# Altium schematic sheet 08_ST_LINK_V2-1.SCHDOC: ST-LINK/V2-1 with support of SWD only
size A4; Date: 17-03-2016; Author: A.B; CompanyName: STMicroelectronics; Organization: Microcontrollers Division; Address1: 12, Rue Jules HOROWITZ; Address2: 38019 Grenoble; Address3: FRANCE; DocumentNumber: 11; Revision: E-01; SheetNumber: 11; SheetTotal: 12; Project: STM32F413H-DISCO
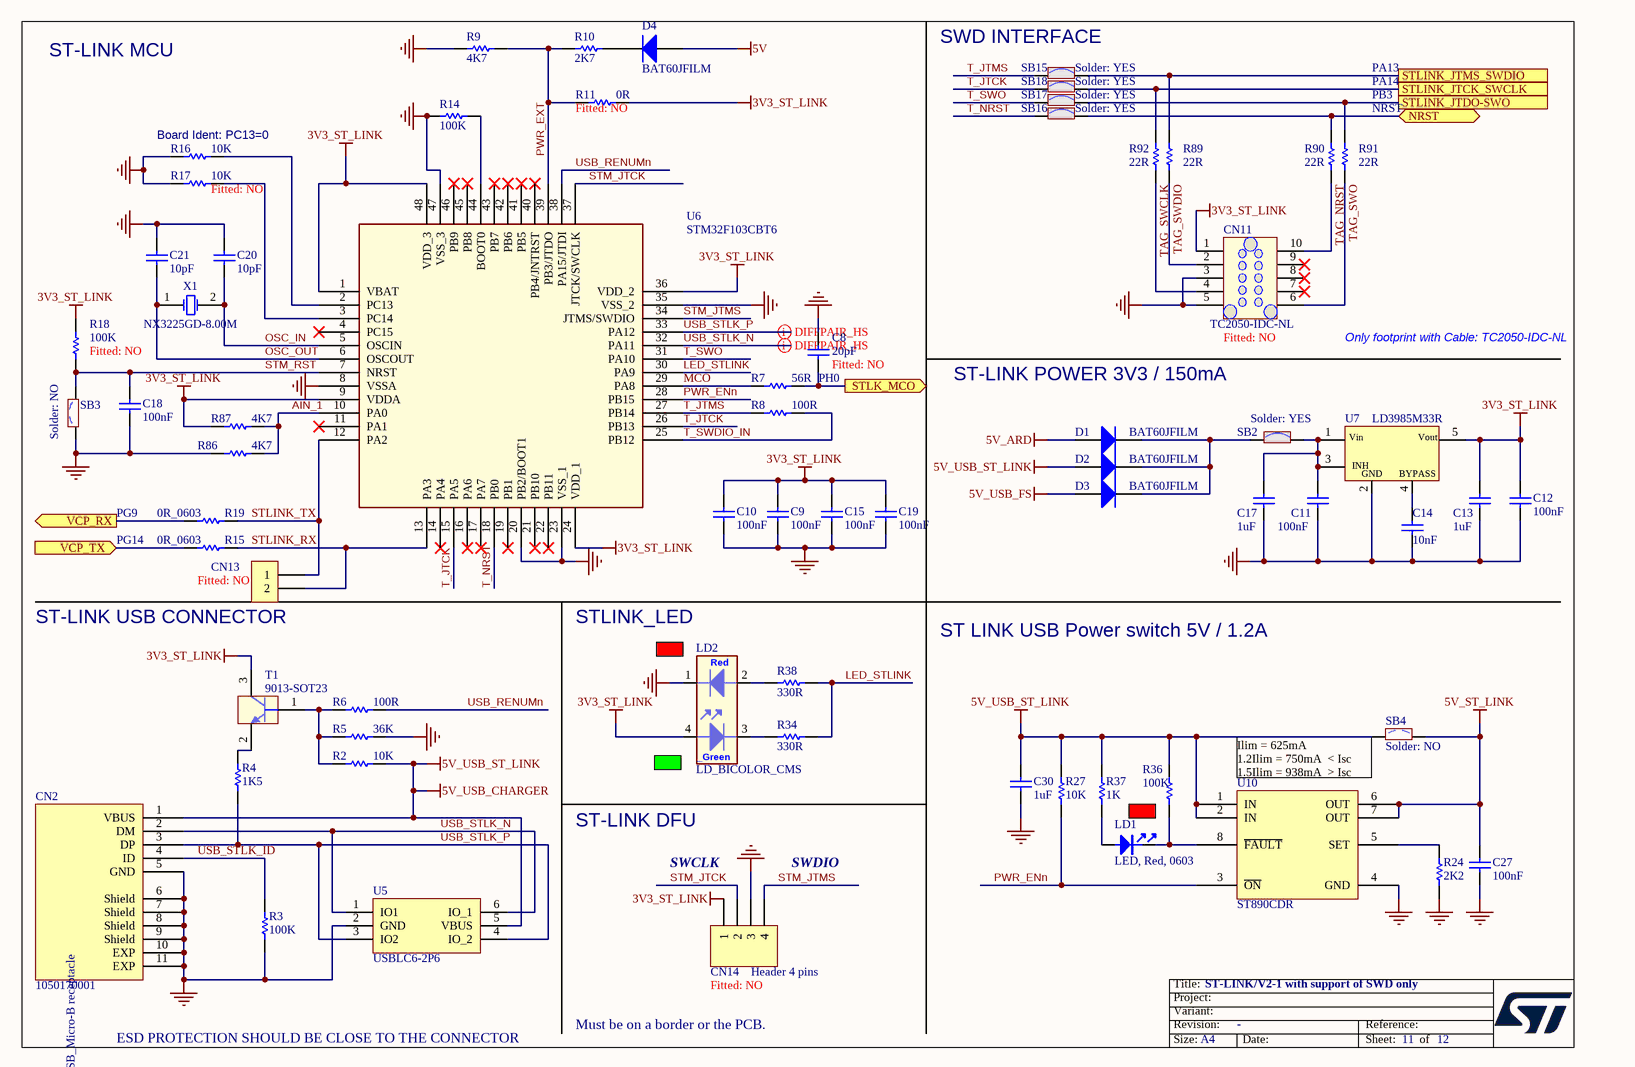
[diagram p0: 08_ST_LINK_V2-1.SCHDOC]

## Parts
C8  20pF  Fitted: NO  [C0402]
C9  100nF  [C0402]
C10  100nF  [C0402]
C11  100nF  [C0402]
C12  100nF  [C0402]
C13  1uF  [C0603]
C14  10nF  [C0603]
C15  100nF  [C0402]
C17  1uF  [C0603]
C18  100nF  [C0402]
C19  100nF  [C0402]
C20  10pF  [C0402]
C21  10pF  [C0402]
C27  100nF  [C0402]
C30  1uF  [C0603]
CN2  1050170001  [CON_USBMICROB_MOLEX_105017-0001_H2P90]
CN11  TC2050-IDC-NL  Fitted: NO  [CON_TAG-C_TC2050-IDC-NL]
CN13  Fitted: NO  [CON_SAMTEC_TSW-102-07-G-S]  (hidden comment: header 2 pins 2.54mm)
CN14  Header 4 pins  Fitted: NO  [CON_SAMTEC_TSW-104-07-G-S]
D1  BAT60JFILM  [DIO_SOD323]
D2  BAT60JFILM  [DIO_SOD323]
D3  BAT60JFILM  [DIO_SOD323]
D4  BAT60JFILM  [DIO_SOD323]
LD1  LED, Red, 0603  [LED_0603_RED]
LD2  LD_BICOLOR_CMS  [LED_BI-GR_HSMF-A201-A00J1]
R2  10K  [R0402]
R3  100K  [R0402]
R4  1K5  [R0402]
R5  36K  [R0402]
R6  100R  [R0402]
R7  56R  [R0402]
R8  100R  [R0402]
R9  4K7  [R0402]
R10  2K7  [R0402]
R11  0R  Fitted: NO  [R0402]
R14  100K  [R0402]
R15  0R_0603  [R0603]
R16  10K  [R0402]
R17  10K  Fitted: NO  [R0402]
R18  100K  Fitted: NO  [R0402]
R19  0R_0603  [R0603]
R24  2K2  [R0402]
R27  10K  [R0402]
R34  330R  [R0402]
R36  100K  [R0402]
R37  1K  [R0402]
R38  330R  [R0402]
R86  4K7  [R0402]
R87  4K7  [R0402]
R89  22R  [R0603]
R90  22R  [R0603]
R91  22R  [R0603]
R92  22R  [R0603]
SB2  Solder: YES  [SOLDER-BRIDGE_R0603-0R]  (hidden comment: SB_ON)
SB3  Solder: NO  [SOLDER-BRIDGE_R0603-0R]  (hidden comment: SB_OFF)
SB4  Solder: NO  [SOLDER-BRIDGE_R0603-0R]  (hidden comment: SB_OFF)
SB15  Solder: YES  [SOLDER-BRIDGE_R0603-0R]  (hidden comment: SB_ON)
SB16  Solder: YES  [SOLDER-BRIDGE_R0603-0R]  (hidden comment: SB_ON)
SB17  Solder: YES  [SOLDER-BRIDGE_R0603-0R]  (hidden comment: SB_ON)
SB18  Solder: YES  [SOLDER-BRIDGE_R0603-0R]  (hidden comment: SB_ON)
T1  9013-SOT23  [NPN_SOT23]
U5  USBLC6-2P6  [ESD_SOT666]
U6  STM32F103CBT6  [ICC_LQFP48_7X7_P050]
U7  LD3985M33R  [REG_SOT23-5L]
U10  ST890CDR  [ICC_SO8_5X4_P127]
X1  NX3225GD-8.00M  [CRY_NX3225GD_2P]

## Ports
NRST (bidir), STLINK_JTCK_SWCLK, STLINK_JTDO-SWO, STLINK_JTMS_SWDIO, STLK_MCO (out), VCP_RX (out), VCP_TX (in)

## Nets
3V3_ST_LINK: C9.2 C10.2 C12.2 C13.2 C15.2 C19.2 CN11.1 CN14.1 LD2.4 R11.2 R18.2 R87.1 T1.3(C) U6.1(VBAT) U6.9(VDDA) U6.24(VDD_1) U6.36(VDD_2) U6.48(VDD_3) U7.5(Vout)
5V: D4.1(A)
5V_ARD: D1.1(A)
5V_ST_LINK: C27.2 SB4.2 U10.6(OUT) U10.7(OUT)
5V_USB_CHARGER: C30.2 CN2.1(VBUS) D2.1(A) R2.1 R27.2 R36.2 R37.2 SB4.1 U5.5(VBUS) U10.1(IN) U10.2(IN)  [also labelled 5V_USB_ST_LINK]
5V_USB_FS: D3.1(A)
GND: C8.1 C9.1 C10.1 C11.1 C12.1 C13.1 C14.1 C15.1 C17.1 C18.1 C19.1 C20.2 C21.2 C27.1 C30.1 CN2.5(GND) CN2.6(Shield) CN2.7(Shield) CN2.8(Shield) CN2.9(Shield) CN2.10(EXP) CN2.11(EXP) CN11.3 CN11.5 CN14.3 LD2.1 R3.1 R5.1 R9.1 R14.1 R16.2 R17.2 R24.1 R86.1 SB3.1 U5.2(GND) U6.8(VSSA) U6.20(PB2/BOOT1) U6.23(VSS_1) U6.35(VSS_2) U6.47(VSS_3) U7.2(GND) U10.4(GND)
AIN_1: R86.2 R87.2 U6.10(PA0)
LED_STLINK: R34.2 R38.2 U6.30(PA9)
MCO: R7.1 U6.29(PA8)
NRST: R90.2 SB16.2 ; port NRST
OSC_IN: C20.1 U6.5(OSCIN) X1.2(OSC2)
OSC_OUT: C21.1 U6.6(OSCOUT) X1.1(OSC1)
PWR_ENn: R27.1 U6.28(PB15) U10.3(~{ON})
PWR_EXT: R9.2 R10.1 R11.1 U6.39(PB3/JTDO)
STLINK_JTCK_SWCLK: R92.2 SB18.2 ; port STLINK_JTCK_SWCLK
STLINK_JTDO-SWO: R91.2 SB17.2 ; port STLINK_JTDO-SWO
STLINK_JTMS_SWDIO: R89.2 SB15.2 ; port STLINK_JTMS_SWDIO
STLINK_RX: CN13.2 R15.2 U6.13(PA3)
STLINK_TX: CN13.1 R19.2 U6.12(PA2)
STLK_MCO: C8.2 R7.2 ; port STLK_MCO
STM_JTCK: CN14.2 U6.37(JTCK/SWCLK)
STM_JTMS: CN14.4 U6.34(JTMS/SWDIO)
STM_RST: C18.2 R18.1 SB3.2 U6.7(NRST)
T_JTCK: SB18.1 U6.15(PA5) U6.26(PB13)
T_JTMS: R8.1 SB15.1 U6.27(PB14)
T_NRST: SB16.1 U6.18(PB0)
T_SWDIO_IN: R8.2 U6.25(PB12)
T_SWO: SB17.1 U6.31(PA10)
TAG_NRST: CN11.10 R90.1
TAG_SWCLK: CN11.4 R92.1
TAG_SWDIO: CN11.2 R89.1
TAG_SWO: CN11.6 R91.1
USB_RENUMn: R6.2 U6.38(PA15/JTDI)
USB_STLK_ID: CN2.4(ID) R3.2
USB_STLK_N: CN2.2(DM) U5.1(IO1) U5.6(IO_1) U6.32(PA11)
USB_STLK_P: CN2.3(DP) R4.1 U5.3(IO2) U5.4(IO_2) U6.33(PA12)
VCP_RX: R19.1 ; port VCP_RX
VCP_TX: R15.1 ; port VCP_TX
NetC11_2: C11.2 C17.2 SB2.2 U7.1(Vin) U7.3(CE)
NetC14_2: C14.2 U7.4(BYPASS)
NetD1_2: D1.2(K) D2.2(K) D3.2(K) SB2.1
NetD4_2: D4.2(K) R10.2
NetLD1_1: LD1.1 R37.1
NetLD1_2: LD1.2 R36.1 U10.8(~{FAULT})
NetLD2_2: LD2.2 R38.1
NetLD2_3: LD2.3 R34.1
NetR2_2: R2.2 R5.2 R6.1 T1.1(B)
NetR4_2: R4.2 T1.2(E)
NetR14_2: R14.2 U6.44(BOOT0)
NetR16_1: R16.1 U6.2(PC13)
NetR17_1: R17.1 U6.3(PC14)
NetR24_2: R24.2 U10.5(SET)

Not connected (* = marked no-connect by the designer): CN11 7* 8* 9*; U6 4(PC15)* 11(PA1)* 14(PA4)* 16(PA6)* 17(PA7)* 19(PB1)* 21(PB10)* 22(PB11)* 40(PB4/JNTRST)* 41(PB5)* 42(PB6)* 43(PB7)* 45(PB8)* 46(PB9)*

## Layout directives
differential pair: USB_STLK_N, USB_STLK_P

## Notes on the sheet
- ST-LINK MCU
- SWD INTERFACE
- PA14
- PA13
- PB3
- NRST
- (near R16) Board Ident: PC13=0
- (near C8) PH0
- ST-LINK POWER 3V3 / 150mA
- Only footprint with Cable: TC2050-IDC-NL
- PG9
- PG14
- ST-LINK USB CONNECTOR
- STLINK_LED
- ST LINK USB Power switch 5V / 1.2A
- (near SB4) Ilim = 625mA
  1.2Ilim = 750mA  < Isc
  1.5Ilim = 938mA  > Isc
- ST-LINK DFU
- SWCLK
- SWDIO
- ESD PROTECTION SHOULD BE CLOSE TO THE CONNECTOR
- Must be on a border or the PCB.

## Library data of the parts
C8 = Cap_20pF_NPO_5%_0402: Capacitor,20pF,50V,NPO,5%,0402,YAGEO; Manuf_Part_1: CC0402JRNPO9BN200; Ordered_By: Subcon
C9-C12 C15 C18 C19 C27 = Cap_100nF_X7R_10%_0402: Capacitor,100nF,16V,X7R,10%,0402,YAGEO; Manuf_Part_1: CC0402KRX7R7BB104; Fitted: YES; Ordered_By: Subcon
C13 C17 C30 = Cap_1uF_X5R_10%_0603: Capacitor,1uF,16V,X5R,10%,0603,YAGEO; Manuf_Part_1: CC0603KRX5R7BB105; Fitted: YES; Ordered_By: Subcon
C14 = Cap_10nF_X7R_10%_0603: Capacitor,10nF,50V,X7R,10%,0603,YAGEO; Manuf_Part_1: CC0603KRX7R9BB103; Fitted: YES; Ordered_By: Subcon
C20 C21 = Cap_10pF_NPO_5%_0402: Capacitor,10pF,50V,NPO,5%,0402,YAGEO; Manuf_Part_1: CC0402JRNPO9BN100; Fitted: YES; Ordered_By: subcon
CN2 = 1050170001: USB-MICRO-B, 1050170001, SMT, MOLEX; Fitted: YES; Ordered_By: Subcon
CN11 = Tag-10-C: Tag_Connector Header, 10-Pin, Dual row No legs; Manuf_Part_1: TC2050-IDC-NL-FP; Ordered_By: Subcon
CN13 = Header 2 pins: Manuf_1: SAMTEC; Manuf_Part_2: 4711955140470; Manuf_2: KONTEC; Manuf_Part_1: TSW-102-07-x-S; Order_Code: 423-2841; Ordered_By: Subcon
CN14 = Header 4: Header, 4-Pin; Manuf_1: SAMTEC; Manuf_Part_1: TSW-104-07-x-S; Ordered_By: Subcon
D1-D4 = BAT60JFILM: Manuf_1: STM; ECCN_US/EU: EAR99/NEC; Ref St: 9151097; Fitted: YES
LD1 = LED_red: Manuf_1: everlight; Manuf_Part_1: 19-213-R6C-AP1Q2B/3T; ECCN_US/EU: EAR99/NEC; Fitted: YES; Ordered_By: Subcon
LD2 = LD_BICOLOR_CMS: Bicolor Led; Manuf_Part_1: HSMF-A201-A00J1; Manuf_1: Avago Technologies; Manuf_2: everluck; Manuf_Part_2: LE-RGW35280; ECCN_US/EU: EAR99/NEC; Fitted: YES; Ordered_By: Subcon
R2 R16 R27 = Res_10K_1%_0402: Resistor,10K,0402,1%,YAGEO; Manuf_Part_1: RC0402FR-0710KL; Fitted: YES; Ordered_By: subcon
R3 R36 = Res_100K_1%_0402: Resistor,100K,0402,1%,YAGEO; Manuf_Part_2: RT0402FRE07100KL; Manuf_Part_1: RC0402FR-07100KL; Fitted: YES; Ordered_By: Subcon
R4 = Res_1K5_1%_0402: Resistor,1K5,0402,1%,YAGEO; Manuf_Part_1: RC0402FR-071K5L; Fitted: YES; Ordered_By: Subcon
R5 = Res_36K_1%_0402: Resistor,36K,0402,1%,YAGEO; Manuf_Part_1: RC0402FR-0736KL; Fitted: YES; Ordered_By: Subcon
R6 R8 = Res_100_1%_0402: Resistor,100R,0402,1%,YAGEO; Manuf_Part_1: RC0402FR-07100RL; Fitted: YES; Order_Code: 9239111; Ordered_By: Subcon
R7 = Res_56_1%_0402: Resistor,56R,0402,1%,YAGEO; Manuf_Part_1: RC0402FR-0756RL; Fitted: YES; Order_Code: 9239081RL; Ordered_By: Subcon
R9 = Res_4K7_1%_0402: Resistor,4K7,0402,1%,YAGEO; Manuf_Part_1: RC0402FR-074K7L; Manuf_Part_2: RT0402FRE074K7L; Fitted: YES; Ordered_By: Subcon
R10 = Res_2K7_1%_0402: Resistor,2K7,0402,1%,YAGEO; Manuf_Part_1: RC0402FR-072K7L; Fitted: YES; Ordered_By: Subcon
R11 = Res_0_5%_0402: Resistor,0R,0402,5%,YAGEO; Manuf_Part_1: RC0402JR-070RL; Order_Code: 2363467; Ordered_By: Subcon
R14 = Res_100K_1%_0402: Resistor,100K,0402,1%,YAGEO; Manuf_Part_1: RC0402FR-07100KL; Manuf_Part_2: RT0402FRE07100KL; Fitted: YES; Ordered_By: Subcon
R15 R19 = Res_0_5%_0603: Resistor,0R,0603,5%,YAGEO; Manuf_Part_1: RC0603JR-070RL; Fitted: YES; Order_Code: 2363481; Ordered_By: subcon
R17 = Res_10K_1%_0402: Resistor,10K,0402,1%,YAGEO; Manuf_Part_1: RC0402FR-0710KL; Ordered_By: subcon
R18 = Res_100K_1%_0402: Resistor,100K,0402,1%,YAGEO; Manuf_Part_1: RC0402FR-07100KL; Manuf_Part_2: RT0402FRE07100KL; Ordered_By: Subcon
R24 = Res_2K2_1%_0402: Resistor,2K2,0402,1%,YAGEO; Manuf_Part_1: RC0402FR-072K2L; Fitted: YES; Ordered_By: Subcon
R34 R38 = Res_330_1%_0402: Resistor,330R,0402,1%,YAGEO; Manuf_Part_1: RC0402FR-07330RL; Fitted: YES; Ordered_By: Subcon
R37 = Res_1K_1%_0402: Resistor,1K,0402,1%,YAGEO; Manuf_Part_1: RC0402FR-071KL; Fitted: YES; Ordered_By: Subcon
R86 R87 = Res_4K7_1%_0402: Resistor,4K7,0402,1%,YAGEO; Manuf_Part_2: RT0402FRE074K7L; Manuf_Part_1: RC0402FR-074K7L; Fitted: YES; Ordered_By: Subcon
R89-R92 = Res_22_1%_0603: Resistor,22R,0603,1%,Yageo; Manuf_Part_1: RC0603FR-0722RL; Fitted: YES; Ordered_By: Subcon
SB2 SB15-SB18 = SB_ON: Solder Bridge ON; Ordered_by: Subcon
SB3 SB4 = SB_OFF: Solder Bridge OFF; Fitted: NO; Ordered_By: Subcon
T1 = 9013-SOT23: NPN Bipolar Transistor; Manuf_1: NXP; Manuf_Part_1: BSR14; ECCN_US/EU: EAR99/NEC; Fitted: YES; Order_Code: 1081310; Ordered_By: Subcon
U5 = USBLC6-2P6: USB ESD protection; Ordered_By: STM; ECCN_US/EU: EAR99; Fitted: YES
U6 = STM32F103CBT6: Medium-density performance line ARM-based 32-bit MCU with 128KB Flash; Manuf_1: STM; ECCN_US/EU: 3A991A2/NEC; Fitted: YES
U7 = LD3985M33R: Ultra low drop-low noise BiCMOS voltage, regulators low ESR capacitors compatible; Manuf_1: STM; Ref St: 9176161; ECCN_US/EU: EAR99/NEC; Fitted: YES
U10 = ST890CDR: 1.2 A current limited high-side power switch with thermal shutdown; Manuf_1: STM; ECCN_US/EU: EAR99/NEC; Fitted: YES
X1 = XTAL_8M_NX3225GD: Crystal 8Mhz, 8pF, -+50PPM, SMD; Manuf_1: NDK; Manuf_Part_1: NX3225GD 8MHz EXS00A-CG04874; ECCN_US/EU: EAR99/NEC; NDK Ref: X3127326; Ref St: 9157029; Fitted: YES; Ordered_By: STM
